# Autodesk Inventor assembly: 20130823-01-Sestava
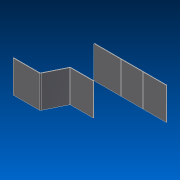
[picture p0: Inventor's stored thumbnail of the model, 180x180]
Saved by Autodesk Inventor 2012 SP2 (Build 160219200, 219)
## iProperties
Created: 2013-08
Part Number: 20130823-01-Sestava
Document SubType Name: Assembly
Designer: navara
Mass: 1.40934 g
Surface Area: 58.0011 cm^2
Volume: 1.40934 cm^3
Density: 1 g/cm^3
Author: navara
LastSaveDate: 12.04.2011
VAHA: 0 kg
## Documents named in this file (3)
- C:\Dokumenty\Zakaznici\__HELPDESK__\HD_20130812\20130823-01-Sestava.iam
- C:\Dokumenty\Zakaznici\__HELPDESK__\HD_20130812\20130823-01-Plech.ipt
- C:\Dokumenty\Zakaznici\__HELPDESK__\HD_20130812\20130823-01-Rozvin.ipt
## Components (2 placed, 2 different names)
1. 20130823-01-Plech:1
2. 20130823-01-Rozvin:1
